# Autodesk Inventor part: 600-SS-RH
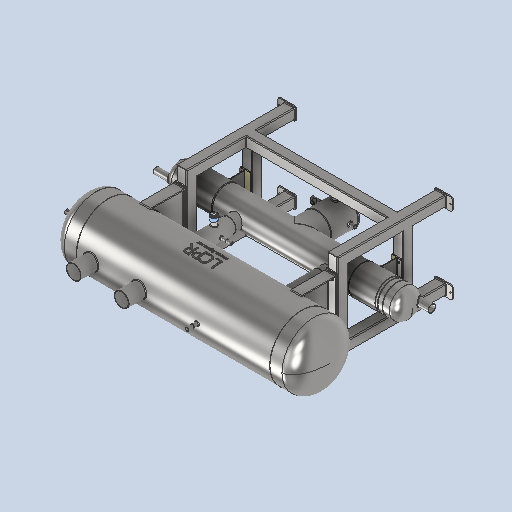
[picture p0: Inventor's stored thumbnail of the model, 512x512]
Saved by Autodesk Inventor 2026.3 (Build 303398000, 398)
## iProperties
Created: 2026-05
Part Number: 600-SS-RH
Material: Generic
Document SubType Name: Modeling
Designer: rva
Density: 1 g/cm^3
Appearance: Default
Author: rva
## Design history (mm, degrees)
derived "LCPR-SS-600-FULL-ASSEMBLY-RH.iam"
body "Solid1"
node "LCPR-SS-600-FULL FRAME ASSEMBLY.iam:1::LCPR-SS-600-FRAME ASS"
node "LCPR-SS-600-1840-125-WELD.iam:1::600 mm Dome End Cap.ipt:1"
node "LCPR-SS-600-1840-125-WELD.iam:1::600 mm Dome End Cap.ipt:2"
node "LCPR-SS-600-1840-125-WELD.iam:1::LPR-600-Leg Assembly.iam:1:"
node "LCPR-SS-600-1840-125-WELD.iam:1::LPR-600-Leg Assembly.iam:2:"
node "LCPR-SS-600-1840-125-WELD.iam:1::H1100-R.ipt:1"
node "LCPR-SS-600-1840-125-WELD.iam:1::LCPR-LOGO.ipt:1"
node "LCPR-SS-600-1840-125-WELD.iam:1::Welds"
node "Sub-SS-250-125-1813-52-65-50-RH.iam:1::SS-LCPR-250 Blank Pla"
node "Sub-SS-250-125-1813-52-65-50-RH.iam:1::SS-250-52 hole Sub Co"
node "Sub-SS-250-125-1813-52-65-50-RH.iam:1::SS-250-52 hole Sub Co"
node "Sub-SS-250-125-1813-52-65-50-RH.iam:1::SS-250 mm Subcooler L"
node "Sub-SS-250-125-1813-52-65-50-RH.iam:1::SS-250 mm Subcooler L"
node "Sub-SS-250-125-1813-52-65-50-RH.iam:1::DIN 2462 Tube 10 x 1 "
node "Sub-SS-250-125-1813-52-65-50-RH.iam:1::DIN 2462 Tube 10 x 1 "
node "Sub-SS-250-125-1813-52-65-50-RH.iam:1::DIN 2462 Tube 10 x 1 "
node "Sub-SS-250-125-1813-52-65-50-RH.iam:1::DIN 2462 Tube 10 x 1 "
node "Sub-SS-250-125-1813-52-65-50-RH.iam:1::DIN 2462 Tube 10 x 1 "
node "Sub-SS-250-125-1813-52-65-50-RH.iam:1::DIN 2462 Tube 10 x 1 "
node "Sub-SS-250-125-1813-52-65-50-RH.iam:1::DIN 2462 Tube 10 x 1 "
node "Sub-SS-250-125-1813-52-65-50-RH.iam:1::DIN 2462 Tube 10 x 1 "
node "Sub-SS-250-125-1813-52-65-50-RH.iam:1::DIN 2462 Tube 10 x 1 "
node "Sub-SS-250-125-1813-52-65-50-RH.iam:1::DIN 2462 Tube 10 x 1 "
node "Sub-SS-250-125-1813-52-65-50-RH.iam:1::DIN 2462 Tube 10 x 1 "
node "Sub-SS-250-125-1813-52-65-50-RH.iam:1::DIN 2462 Tube 10 x 1 "
node "Sub-SS-250-125-1813-52-65-50-RH.iam:1::DIN 2462 Tube 10 x 1 "
node "Sub-SS-250-125-1813-52-65-50-RH.iam:1::DIN 2462 Tube 10 x 1 "
node "Sub-SS-250-125-1813-52-65-50-RH.iam:1::H1100-R.ipt:1"
node "Sub-SS-250-125-1813-52-65-50-RH.iam:1::H1100-R.ipt:2"
node "Sub-SS-250-125-1813-52-65-50-RH.iam:1::1-2 Inch NPT Socket -"
node "Sub-SS-250-125-1813-52-65-50-RH.iam:1::1-2 Inch NPT Socket -"
node "Sub-SS-250-125-1813-52-65-50-RH.iam:1::3-4 Inch NPT Socket -"
node "Sub-SS-250-125-1813-52-65-50-RH.iam:1::Welds"
node "AS 1111 - Metric M8 x 130:1"
node "AS 1111 - Metric M8 x 130:2"
node "AS 1111 - Metric M8 x 130:3"
node "AS 1111 - Metric M8 x 130:4"
node "AS 1111 - Metric M10 x 130:1"
node "AS 1111 - Metric M10 x 130:2"
node "AS 1111 - Metric M10 x 130:3"
node "AS 1111 - Metric M10 x 130:4"
node "AS 1112 (4) - Metric M10:1"
node "AS 1112 (4) - Metric M10:2"
node "AS 1112 (4) - Metric M10:3"
node "AS 1112 (4) - Metric M10:4"
node "AS 1112 (4) - Metric M8:1"
node "AS 1112 (4) - Metric M8:2"
node "AS 1112 (4) - Metric M8:3"
node "AS 1112 (4) - Metric M8:4"
node "AS 1237 (4.1) 8 mm:1"
node "AS 1237 (4.1) 8 mm:2"
node "AS 1237 (4.1) 8 mm:3"
node "AS 1237 (4.1) 8 mm:4"
node "AS 1237 (4.1) 8 mm:5"
node "AS 1237 (4.1) 8 mm:6"
node "AS 1237 (4.1) 8 mm:7"
node "AS 1237 (4.1) 8 mm:8"
node "AS 1237 (4.1) 10 mm:1"
node "AS 1237 (4.1) 10 mm:2"
node "AS 1237 (4.1) 10 mm:3"
node "AS 1237 (4.1) 10 mm:4"
node "AS 1237 (4.1) 10 mm:5"
node "AS 1237 (4.1) 10 mm:6"
node "AS 1237 (4.1) 10 mm:7"
node "AS 1237 (4.1) 10 mm:8"
node "Nylon Heat Tranfer Spacer 568x100.ipt:1"
node "Nylon Heat Tranfer Spacer 568x100.ipt:2"
node "Nylon Heat Tranfer Spacer 175x100.ipt:1"
node "Nylon Heat Tranfer Spacer 175x100.ipt:2"
node "LCPR-SS-600-FULL-ASSEMBLY-RH.iam_Bodies"
